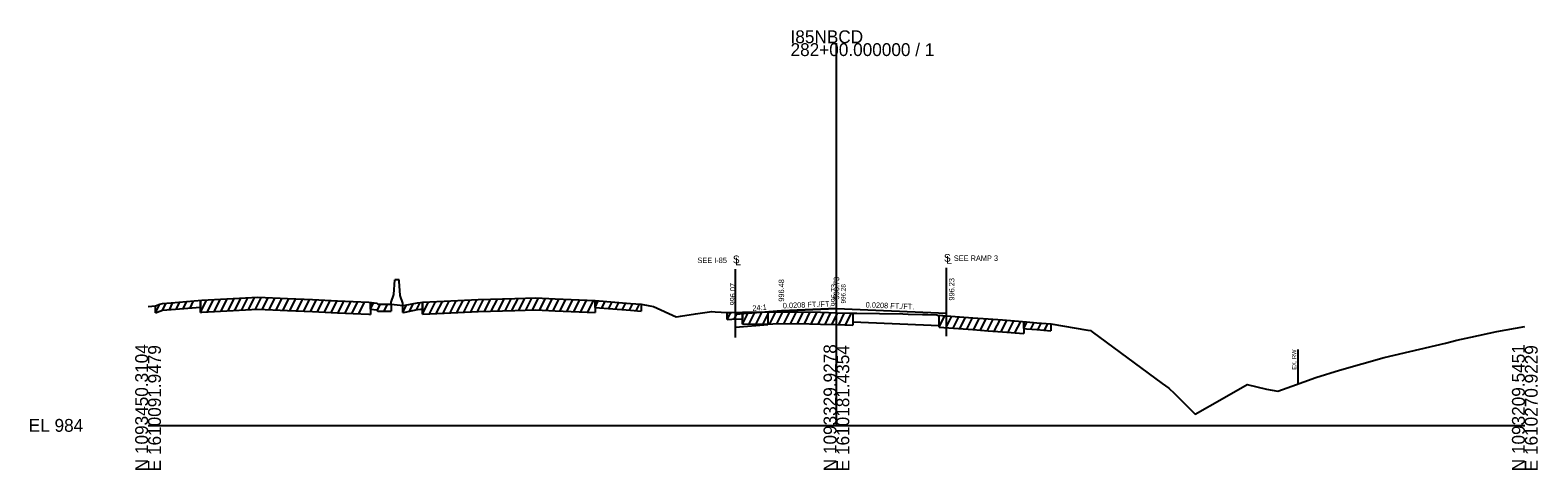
# Model space of a CAD drawing. Extents: x -26 to 1615432, y -20 to 1281970.
# Drawn here: x 974.3 to 1302.8, y 8990.3 to 9086.1 of the extents above; entities that cross this region are included whole.
import ezdxf

# ---------------------------------------------------------------- set-up
doc = ezdxf.new("R2010")
doc.units = 0
for name, color, linetype in [('CLS_MSE_MS_Wall', 7, 'Continuous'), ('CLS_Slope_MSE', 7, 'Continuous'), ('HY_DR_DumbNodes', 7, 'Continuous'), ('RD_EX_Misc', 7, 'Continuous'), ('RD_GPK_XS_Cell', 7, 'Continuous'), ('RD_PD_DR_FlowCtrl', 7, 'Continuous'), ('RD_Sketch1', 7, 'Continuous'), ('RD_XE_Ground', 7, 'Continuous'), ('RD_XS_Base', 7, 'Continuous'), ('RD_XS_ExGround', 7, 'Continuous'), ('RD_XS_ExPaveRet', 7, 'Continuous'), ('RD_XS_MatchLine', 7, 'Continuous'), ('RD_XS_Pave', 7, 'Continuous'), ('RD_XS_PaveShd', 7, 'Continuous'), ('RD_XS_TX_Elev_EX', 7, 'Continuous'), ('RD_XS_TX_Elev_PR', 7, 'Continuous'), ('RD_XS_TX_MatchLine', 7, 'Continuous'), ('RD_XS_TX_ShdSlope', 7, 'Continuous'), ('RD_XS_TX_Slope', 7, 'Continuous')]:
    doc.layers.add(name, color=color, linetype=linetype)

msp = doc.modelspace()

# ---------------------------------------------------------------- linework, layer by layer
at = {"layer": 'CLS_Slope_MSE'}
msp.add_line((1250.54, 9016.51), (1250.54, 9008.99), dxfattribs=at)
at = {"layer": 'HY_DR_DumbNodes'}
for p, q in [((1138, 9024.96), (1150, 9025.46)), ((1150, 9025.46), (1162, 9024.96))]:
    msp.add_line(p, q, dxfattribs=at)
at = {"layer": 'RD_EX_Misc'}
for p, q in [((1001.65, 9024.53), (1001.65, 9026.03)), ((1001.65, 9024.53), (1002.59, 9024.89)), ((1002.59, 9024.89), (1003.14, 9025.08)), ((1003.14, 9025.08), (1005.01, 9025.23)), ((1005.01, 9025.23), (1011.42, 9025.73)), ((1011.42, 9027.23), (1011.42, 9025.73)), ((1048.45, 9025.3), (1048.45, 9026.8)), ((1048.45, 9025.3), (1049.86, 9025.15)), ((1049.86, 9025.15), (1050.07, 9024.92)), ((1050.07, 9024.92), (1052.98, 9024.88)), ((1052.98, 9024.88), (1052.99, 9024.88)), ((1052.99, 9026.38), (1052.99, 9024.88)), ((1055.5, 9024.63), (1055.5, 9026.13)), ((1056.02, 9024.68), (1058.72, 9025.23)), ((1058.72, 9025.23), (1059.38, 9025.29)), ((1059.38, 9025.29), (1059.8, 9025.33)), ((1059.8, 9026.83), (1059.8, 9025.33)), ((1097.39, 9025.71), (1097.39, 9027.21)), ((1097.39, 9025.71), (1105.12, 9025.09)), ((1105.12, 9025.09), (1107.46, 9024.91)), ((1107.46, 9026.41), (1107.46, 9024.91)), ((1055.5, 9024.63), (1055.59, 9024.62)), ((1055.59, 9024.62), (1056.02, 9024.68)), ((1126.21, 9023.08), (1126.21, 9024.58)), ((1126.21, 9023.08), (1127.17, 9023.12)), ((1127.17, 9023.12), (1129.51, 9023.19)), ((1129.51, 9024.69), (1129.51, 9023.19)), ((1190.87, 9021.1), (1190.87, 9022.6)), ((1196.75, 9022.1), (1196.75, 9020.6)), ((1190.87, 9021.1), (1191.41, 9021.06)), ((1191.41, 9021.06), (1193.7, 9020.86)), ((1193.7, 9020.86), (1196.75, 9020.6)), ((1196.75, 9020.6), (1196.75, 9020.6))]:
    msp.add_line(p, q, dxfattribs=at)
at = {"layer": 'RD_GPK_XS_Cell'}
for p, q in [((1150, 9000), (1150, 9083.29)), ((1000, 9000), (1150, 9000)), ((1150, 9000), (1300, 9000))]:
    msp.add_line(p, q, dxfattribs=at)
at = {"layer": 'RD_PD_DR_FlowCtrl'}
for p, q in [((1138, 9024.96), (1150, 9025.46)), ((1150, 9025.46), (1162, 9024.96))]:
    msp.add_line(p, q, dxfattribs=at)
at = {"layer": 'RD_Sketch1'}
for p, q in [((1001.65, 9024.53), (1002.57, 9026.38)), ((1003.15, 9025.08), (1003.93, 9026.64)), ((1004.65, 9025.2), (1005.43, 9026.76)), ((1006.15, 9025.32), (1006.93, 9026.88)), ((1007.65, 9025.44), (1008.43, 9027)), ((1009.15, 9025.55), (1009.93, 9027.12)), ((1048.45, 9025.3), (1049.16, 9026.72)), ((1049.95, 9025.05), (1050.63, 9026.41)), ((1051.45, 9024.9), (1052.19, 9026.39)), ((1055.5, 9024.63), (1056.31, 9026.24)), ((1057, 9024.88), (1057.84, 9026.55)), ((1058.5, 9025.19), (1059.3, 9026.79)), ((1097.39, 9025.71), (1098.11, 9027.15)), ((1098.89, 9025.59), (1099.61, 9027.03)), ((1100.39, 9025.47), (1101.11, 9026.91)), ((1101.89, 9025.35), (1102.61, 9026.79)), ((1103.39, 9025.23), (1104.11, 9026.67)), ((1104.89, 9025.11), (1105.61, 9026.55)), ((1106.39, 9024.99), (1107.11, 9026.43)), ((1126.21, 9023.08), (1126.98, 9024.61)), ((1127.71, 9023.13), (1128.48, 9024.66)), ((1190.87, 9021.1), (1191.59, 9022.54)), ((1192.37, 9020.97), (1193.09, 9022.41)), ((1193.87, 9020.84), (1194.59, 9022.28)), ((1195.37, 9020.72), (1196.09, 9022.15))]:
    msp.add_line(p, q, dxfattribs=at)
at = {"layer": 'RD_XE_Ground'}
for p, q in [((1053.57, 9028.55), (1053.74, 9031.71)), ((1054.75, 9031.71), (1053.74, 9031.71)), ((1054.75, 9031.46), (1054.75, 9031.71)), ((1054.92, 9028.3), (1054.75, 9031.46)), ((1052.99, 9026.88), (1053.57, 9028.55)), ((1055.5, 9026.63), (1054.92, 9028.3)), ((1052.99, 9026.38), (1052.99, 9026.88)), ((1055.5, 9026.13), (1055.5, 9026.63))]:
    msp.add_line(p, q, dxfattribs=at)
at = {"layer": 'RD_XS_Base'}
for p, q in [((1128, 9021.35), (1128, 9024.13)), ((1135.04, 9021.94), (1128, 9021.35)), ((1135.04, 9024.72), (1136.15, 9024.72)), ((1135.04, 9024.72), (1135.04, 9021.94)), ((1136.15, 9024.72), (1138, 9024.74)), ((1138, 9024.74), (1141.69, 9024.78)), ((1141.69, 9024.78), (1146.54, 9024.65)), ((1146.54, 9024.65), (1150, 9024.56)), ((1150, 9024.56), (1153.55, 9024.46)), ((1153.55, 9024.46), (1153.55, 9022.54)), ((1153.55, 9022.54), (1172.4, 9021.75)), ((1172.4, 9024.02), (1174, 9023.9)), ((1172.4, 9021.75), (1172.4, 9024.02))]:
    msp.add_line(p, q, dxfattribs=at)
at = {"layer": 'RD_XS_ExGround'}
msp.add_lwpolyline([(1000, 9025.88), (1001.65, 9026.03), (1002.59, 9026.39), (1003.14, 9026.58), (1005.01, 9026.73), (1011.71, 9027.26), (1018.51, 9027.65), (1023.94, 9027.95), (1030.35, 9027.66), (1035.84, 9027.42), (1041.3, 9027.16), (1048.11, 9026.84), (1049.86, 9026.65), (1050.07, 9026.42), (1052.98, 9026.38), (1055.59, 9026.12), (1056.02, 9026.18), (1058.72, 9026.73), (1059.38, 9026.79), (1059.8, 9026.83), (1064.54, 9027.04), (1071.92, 9027.4), (1079.95, 9027.63), (1084.48, 9027.77), (1088.68, 9027.59), (1097.39, 9027.21), (1105.12, 9026.59), (1107.46, 9026.41), (1109.33, 9026.07), (1110.14, 9025.91), (1115.11, 9023.65), (1115.58, 9023.7), (1116.04, 9023.78), (1119.26, 9024.28), (1122.88, 9024.81), (1123.59, 9024.76), (1126.21, 9024.58), (1127.17, 9024.62), (1129.51, 9024.69), (1136.15, 9024.72), (1141.69, 9024.78), (1146.54, 9024.65), (1150, 9024.56), (1153.86, 9024.45), (1154.42, 9024.46), (1159.41, 9024.41), (1164.47, 9024.33), (1165.63, 9024.27), (1168.72, 9024.2), (1169.93, 9024.16), (1171.91, 9024.1), (1172.01, 9024.05), (1179.69, 9023.46), (1183.07, 9023.24), (1186.19, 9022.99), (1191.41, 9022.56), (1193.7, 9022.36), (1196.75, 9022.1), (1204.78, 9020.77), (1205.35, 9020.67), (1205.73, 9020.35), (1221, 9009.16), (1222.46, 9008.13), (1223.68, 9006.97), (1226, 9004.6), (1228.15, 9002.41), (1234.07, 9005.77), (1239.47, 9008.91), (1243.68, 9007.88), (1246.16, 9007.48), (1249.2, 9008.51), (1254.47, 9010.41), (1259.61, 9012), (1269.35, 9014.8), (1282.69, 9017.88), (1285.21, 9018.54), (1288.25, 9019.24), (1293.88, 9020.47), (1300, 9021.57)], dxfattribs=at)
at = {"layer": 'RD_XS_ExPaveRet'}
for p, q in [((1011.42, 9024.63), (1012.76, 9027.32)), ((1011.42, 9024.63), (1011.42, 9027.23)), ((1011.71, 9024.66), (1018.51, 9025.05)), ((1012.92, 9024.73), (1014.25, 9027.4)), ((1014.42, 9024.81), (1015.75, 9027.49)), ((1015.92, 9024.9), (1017.25, 9027.58)), ((1017.42, 9024.99), (1018.75, 9027.66)), ((1018.51, 9025.05), (1023.94, 9025.35)), ((1018.92, 9025.07), (1020.25, 9027.75)), ((1020.42, 9025.16), (1021.75, 9027.83)), ((1021.92, 9025.24), (1023.25, 9027.91)), ((1023.42, 9025.32), (1024.71, 9027.92)), ((1023.94, 9025.35), (1030.35, 9025.06)), ((1024.92, 9025.31), (1026.19, 9027.85)), ((1026.42, 9025.24), (1027.69, 9027.78)), ((1027.92, 9025.17), (1029.19, 9027.71)), ((1029.42, 9025.1), (1030.69, 9027.65)), ((1030.35, 9025.06), (1035.84, 9024.82)), ((1030.92, 9025.04), (1032.19, 9027.58)), ((1032.42, 9024.97), (1033.69, 9027.52)), ((1033.92, 9024.91), (1035.19, 9027.45)), ((1035.42, 9024.84), (1036.69, 9027.38)), ((1035.84, 9024.82), (1041.3, 9024.56)), ((1036.92, 9024.77), (1038.19, 9027.31)), ((1038.42, 9024.7), (1039.69, 9027.24)), ((1039.92, 9024.63), (1041.19, 9027.17)), ((1041.42, 9024.56), (1042.69, 9027.1)), ((1042.92, 9024.48), (1044.19, 9027.02)), ((1044.42, 9024.41), (1045.69, 9026.95)), ((1045.92, 9024.34), (1047.19, 9026.88)), ((1048.45, 9026.8), (1048.45, 9024.2)), ((1059.8, 9024.23), (1061.13, 9026.89)), ((1059.8, 9024.23), (1059.8, 9026.83)), ((1061.3, 9024.29), (1062.63, 9026.95)), ((1062.8, 9024.36), (1064.13, 9027.02)), ((1064.3, 9024.43), (1065.63, 9027.09)), ((1064.54, 9024.44), (1071.92, 9024.8)), ((1065.8, 9024.5), (1067.13, 9027.16)), ((1067.3, 9024.57), (1068.63, 9027.24)), ((1068.8, 9024.64), (1070.13, 9027.31)), ((1070.3, 9024.72), (1071.63, 9027.38)), ((1071.8, 9024.79), (1073.12, 9027.43)), ((1071.92, 9024.8), (1079.95, 9025.03)), ((1073.3, 9024.84), (1074.62, 9027.48)), ((1074.8, 9024.88), (1076.12, 9027.52)), ((1076.3, 9024.92), (1077.62, 9027.56)), ((1077.8, 9024.97), (1079.12, 9027.61)), ((1079.3, 9025.01), (1080.62, 9027.65)), ((1079.95, 9025.03), (1084.48, 9025.17)), ((1080.8, 9025.06), (1082.12, 9027.7)), ((1082.3, 9025.1), (1083.62, 9027.74)), ((1083.8, 9025.15), (1085.09, 9027.74)), ((1084.48, 9025.17), (1088.68, 9024.99)), ((1085.3, 9025.13), (1086.57, 9027.68)), ((1086.8, 9025.07), (1088.07, 9027.61)), ((1088.3, 9025), (1089.57, 9027.55)), ((1088.68, 9024.99), (1097.39, 9024.61)), ((1089.8, 9024.94), (1091.07, 9027.48)), ((1091.3, 9024.87), (1092.57, 9027.42)), ((1092.8, 9024.81), (1094.07, 9027.36)), ((1094.3, 9024.75), (1095.57, 9027.29)), ((1095.8, 9024.68), (1097.07, 9027.23)), ((1097.39, 9027.21), (1097.39, 9024.61)), ((1011.42, 9024.63), (1011.71, 9024.66)), ((1041.3, 9024.56), (1048.11, 9024.24)), ((1048.11, 9024.24), (1048.45, 9024.2)), ((1059.8, 9024.23), (1064.54, 9024.44)), ((1129.51, 9022.09), (1130.81, 9024.7)), ((1129.51, 9022.09), (1129.51, 9024.69)), ((1129.51, 9022.09), (1136.15, 9022.12)), ((1131.01, 9022.1), (1132.31, 9024.71)), ((1132.51, 9022.11), (1133.81, 9024.71)), ((1134.01, 9022.11), (1135.31, 9024.72)), ((1135.51, 9022.12), (1136.81, 9024.73)), ((1136.15, 9022.12), (1141.69, 9022.18)), ((1137.01, 9022.13), (1138.32, 9024.74)), ((1138.51, 9022.15), (1139.82, 9024.76)), ((1140.01, 9022.16), (1141.32, 9024.78)), ((1141.51, 9022.18), (1142.8, 9024.75)), ((1141.69, 9022.18), (1146.54, 9022.05)), ((1143.01, 9022.14), (1144.29, 9024.71)), ((1144.51, 9022.1), (1145.79, 9024.67)), ((1146.01, 9022.06), (1147.29, 9024.63)), ((1146.54, 9022.05), (1150, 9021.96)), ((1147.51, 9022.02), (1148.79, 9024.59)), ((1149.01, 9021.98), (1150.29, 9024.55)), ((1150, 9021.96), (1153.55, 9021.86)), ((1150.51, 9021.94), (1151.79, 9024.51)), ((1152.01, 9021.9), (1153.29, 9024.47)), ((1153.55, 9024.46), (1153.55, 9021.86)), ((1172.4, 9021.42), (1172.4, 9024.02)), ((1172.4, 9021.42), (1173.65, 9023.93)), ((1173.9, 9021.31), (1175.15, 9023.81)), ((1175.4, 9021.19), (1176.65, 9023.69)), ((1176.9, 9021.07), (1178.15, 9023.58)), ((1178.4, 9020.96), (1179.65, 9023.46)), ((1179.9, 9020.84), (1181.16, 9023.36)), ((1181.4, 9020.75), (1182.66, 9023.26)), ((1182.9, 9020.65), (1184.15, 9023.15)), ((1184.4, 9020.53), (1185.65, 9023.03)), ((1185.9, 9020.41), (1187.15, 9022.91)), ((1187.4, 9020.29), (1188.65, 9022.79)), ((1188.9, 9020.17), (1190.15, 9022.66)), ((1190.87, 9022.6), (1190.87, 9020)), ((1172.4, 9021.42), (1179.69, 9020.86)), ((1179.69, 9020.86), (1183.07, 9020.64)), ((1183.07, 9020.64), (1186.19, 9020.39)), ((1186.19, 9020.39), (1190.87, 9020))]:
    msp.add_line(p, q, dxfattribs=at)
at = {"layer": 'RD_XS_MatchLine'}
for p, q in [((1128, 9024.64), (1128, 9024.13)), ((1174, 9023.9), (1174, 9024.46))]:
    msp.add_line(p, q, dxfattribs=at)
at = {"layer": 'RD_XS_Pave'}
for q in [(1138, 9024.96), (1174, 9024.46)]:
    msp.add_line((1150, 9025.46), q, dxfattribs=at)
at = {"layer": 'RD_XS_PaveShd'}
msp.add_line((1138, 9024.96), (1128, 9024.13), dxfattribs=at)
at = {"layer": 'RD_XS_TX_MatchLine'}
for p, q in [((1128, 9024.13), (1128, 9034.02)), ((1174, 9024.46), (1174, 9034.35)), ((1128, 9019.13), (1128, 9024.13)), ((1174, 9019.46), (1174, 9024.46))]:
    msp.add_line(p, q, dxfattribs=at)

# ---------------------------------------------------------------- texts
at = {"layer": 'CLS_MSE_MS_Wall'}
for s, p in [('SEE I-85', (1119.71, 9035.37)), ('SEE RAMP 3', (1175.58, 9035.83))]:
    msp.add_text(s, height=1.2, dxfattribs=at).set_placement(p)
at = {"layer": 'CLS_Slope_MSE'}
msp.add_text('EX. RW', height=0.9, rotation=90, dxfattribs=at).set_placement((1250.18, 9012.11))
at = {"layer": 'HY_DR_DumbNodes'}
msp.add_text(' 996.73', height=1.2, rotation=90, dxfattribs=at).set_placement((1150, 9025.46))
at = {"layer": 'RD_GPK_XS_Cell'}
for s, p in [('I85NBCD', (1140, 9083.29)), ('282+00.000000 / 1', (1140, 9080.49)), ('EL 984', (974, 8998.6))]:
    msp.add_text(s, height=2.8, dxfattribs=at).set_placement(p)
for s, p in [('N 1093450.3104', (1000, 8990)), ('E 1610091.9479', (1002.8, 8990)), ('N 1093329.9278', (1150, 8990)), ('E 1610181.4354', (1152.8, 8990)), ('N 1093209.5451', (1300, 8990)), ('E 1610270.9229', (1302.8, 8990))]:
    msp.add_text(s, height=2.8, rotation=90, dxfattribs=at).set_placement(p)
at = {"layer": 'RD_PD_DR_FlowCtrl'}
msp.add_text(' 996.73', height=1.2, rotation=90, dxfattribs=at).set_placement((1150, 9025.46))
at = {"layer": 'RD_XS_TX_Elev_EX'}
msp.add_text('996.28', height=1, rotation=90, dxfattribs=at).set_placement((1152, 9026.56))
at = {"layer": 'RD_XS_TX_Elev_PR'}
for s, p in [('996.48', (1138.6, 9026.96)), ('996.73', (1150.6, 9027.46)), ('996.23', (1175.71, 9027.2)), ('996.07', (1128, 9026.13))]:
    msp.add_text(s, height=1.2, rotation=90, dxfattribs=at).set_placement(p)
at = {"layer": 'RD_XS_TX_MatchLine'}
for s, p in [('S', (1127.42, 9035.33)), ('L', (1127.93, 9034.9)), ('S', (1173.42, 9035.67)), ('L', (1173.93, 9035.23))]:
    msp.add_text(s, height=1.68, dxfattribs=at).set_placement(p)
at = {"layer": 'RD_XS_TX_ShdSlope'}
msp.add_text('24:1', height=1.2, rotation=4.7636, dxfattribs=at).set_placement((1131.75, 9024.94))
at = {"layer": 'RD_XS_TX_Slope'}
for rotation, p in [(2.3859, (1138.34, 9025.48)), (357.6141, (1156.35, 9025.7))]:
    msp.add_text('0.0208 FT./FT.', height=1.2, rotation=rotation, dxfattribs=at).set_placement(p)

doc.saveas('drawing.dxf')
